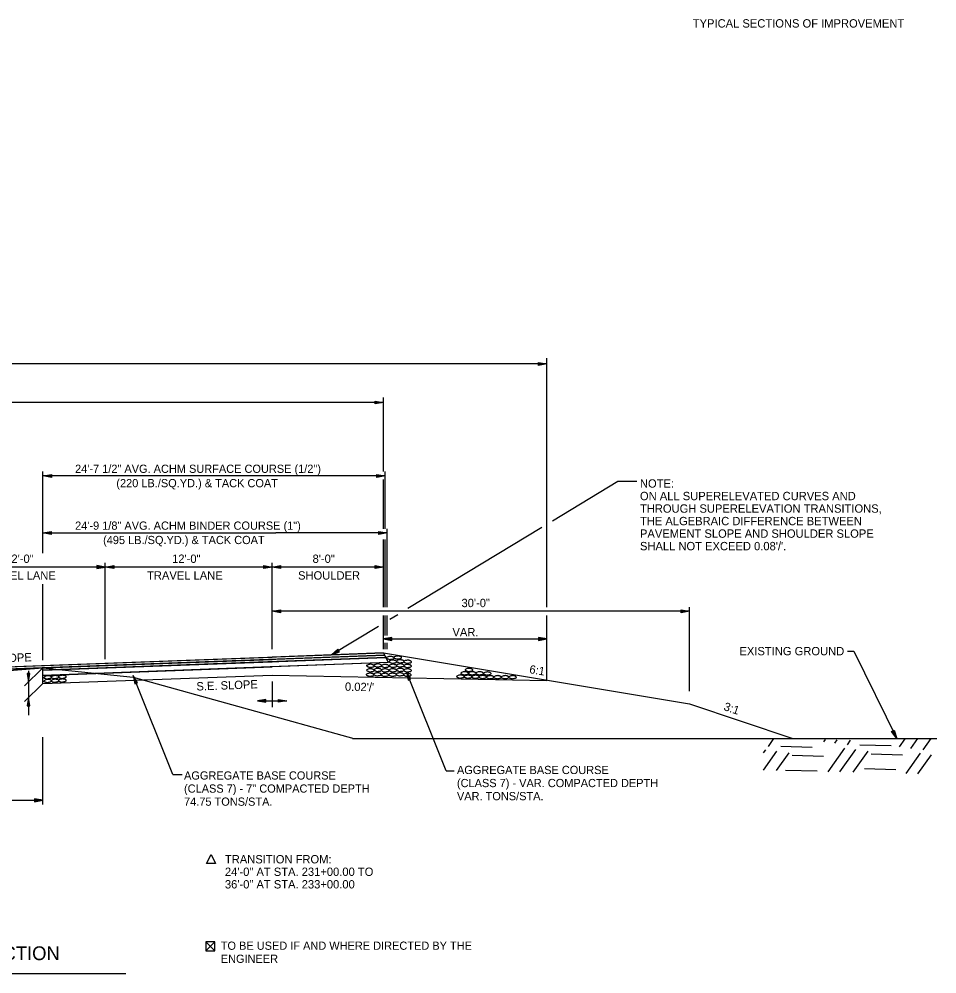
# Model space of a CAD drawing. Extents: x 1461846 to 1462006, y 1686171 to 1686805.
# Drawn here: x 1461938.5 to 1462004.5, y 1686332.5 to 1686401.2 of the extents above; entities that cross this region are included whole.
import ezdxf

# ---------------------------------------------------------------- set-up
doc = ezdxf.new("R2010")
doc.units = 0
for name, color, linetype in [('1', 7, 'Continuous'), ('10', 7, 'Continuous'), ('12', 7, 'Continuous'), ('19', 7, 'Continuous'), ('20', 7, 'Continuous'), ('3', 7, 'Continuous'), ('42', 7, 'Continuous'), ('R_Draft', 7, 'Continuous')]:
    doc.layers.add(name, color=color, linetype=linetype)

# ---------------------------------------------------------------- blocks, each defined once
blk = doc.blocks.new('ROCKS')
at = {"layer": '1'}
blk.add_spline([(0.013, 0.06), (0.053, 0.053), (0.107, 0.033), (0.133, 0.013), (0.133, -0.007), (0.12, -0.033), (0.107, -0.04), (0.073, -0.053), (0.033, -0.067), (0.013, -0.067), (-0.02, -0.06), (-0.06, -0.053), (-0.087, -0.047), (-0.113, -0.02), (-0.113, -0.007), (-0.107, 0.02), (-0.087, 0.033), (-0.067, 0.047), (-0.033, 0.053), (-0.02, 0.06), (0.013, 0.06)], degree=3, dxfattribs=at)

msp = doc.modelspace()

# ---------------------------------------------------------------- linework, layer by layer
at = {"layer": '10'}
for p, q in [((1461951.906, 1686334.857), (1461952.547, 1686334.216)), ((1461952.547, 1686334.857), (1461951.906, 1686334.216)), ((1461952.287, 1686334.216), (1461952.298, 1686334.216))]:
    msp.add_line(p, q, dxfattribs=at)
for points in [[(1461952.601, 1686340.482), (1461951.959, 1686340.482), (1461952.28, 1686341.123), (1461952.601, 1686340.482)], [(1461952.298, 1686334.216), (1461952.547, 1686334.216), (1461952.547, 1686334.857), (1461951.906, 1686334.857), (1461951.906, 1686334.216), (1461952.287, 1686334.216)]]:
    msp.add_lwpolyline(points, dxfattribs=at)
at = {"layer": '19'}
for p, q in [((1461964.68, 1686355.622), (1461965.028, 1686354.927)), ((1461964.844, 1686355.295), (1461965.028, 1686354.927)), ((1461940.18, 1686354.007), (1461940.18, 1686354.382)), ((1461940.18, 1686354.382), (1461940.18, 1686354.382)), ((1461939.261, 1686354.147), (1461939.051, 1686354.147)), ((1461939.051, 1686354.147), (1461939.156, 1686353.547)), ((1461939.106, 1686354.147), (1461939.141, 1686353.707)), ((1461939.156, 1686353.547), (1461939.261, 1686354.147)), ((1461939.171, 1686353.707), (1461939.211, 1686354.147)), ((1461940.18, 1686354.007), (1461940.18, 1686354.007)), ((1461949.537, 1686346.872), (1461946.684, 1686353.991)), ((1461947.004, 1686353.475), (1461946.684, 1686353.991)), ((1461946.684, 1686353.991), (1461946.811, 1686353.395)), ((1461946.732, 1686353.839), (1461946.859, 1686353.418)), ((1461946.958, 1686353.457), (1461946.759, 1686353.85)), ((1461969.184, 1686347.148), (1461966.332, 1686354.268)), ((1461966.651, 1686353.751), (1461966.332, 1686354.268)), ((1461966.332, 1686354.268), (1461966.458, 1686353.672)), ((1461966.379, 1686354.116), (1461966.506, 1686353.695)), ((1461966.605, 1686353.733), (1461966.406, 1686354.126)), ((1461966.458, 1686353.672), (1461966.651, 1686353.751)), ((1461946.811, 1686353.395), (1461947.004, 1686353.475)), ((1461939.156, 1686352.422), (1461939.051, 1686351.822)), ((1461939.141, 1686352.262), (1461939.101, 1686351.822)), ((1461939.261, 1686351.822), (1461939.156, 1686352.422)), ((1461939.206, 1686351.822), (1461939.171, 1686352.262)), ((1461939.051, 1686351.822), (1461939.261, 1686351.822)), ((1461992.352, 1686348.904), (1461992.758, 1686349.478)), ((1461993.241, 1686348.922), (1461995.5, 1686348.845)), ((1461996.347, 1686349.241), (1461996.456, 1686349.389)), ((1461997.139, 1686349.13), (1461997.311, 1686349.37)), ((1461998.032, 1686349.016), (1461998.266, 1686349.349)), ((1461998.92, 1686349.024), (1462001.18, 1686348.958)), ((1462001.793, 1686348.869), (1462002.2, 1686349.451)), ((1462002.586, 1686348.758), (1462003.091, 1686349.464)), ((1462003.479, 1686348.644), (1462004.061, 1686349.478)), ((1461991.993, 1686347.196), (1461992.953, 1686348.555)), ((1461992.001, 1686348.445), (1461992.16, 1686348.667)), ((1461992.948, 1686347.175), (1461993.845, 1686348.442)), ((1461994.066, 1686348.272), (1461996.324, 1686348.196)), ((1461996.646, 1686347.086), (1461997.84, 1686348.779)), ((1461997.501, 1686347.068), (1461998.633, 1686348.668)), ((1461998.456, 1686347.047), (1461999.525, 1686348.554)), ((1461999.734, 1686348.376), (1462002.004, 1686348.308)), ((1462002.255, 1686346.955), (1462003.287, 1686348.406)), ((1462003.11, 1686346.937), (1462004.079, 1686348.295)), ((1461949.537, 1686346.872), (1461950.214, 1686346.872)), ((1461969.184, 1686347.148), (1461969.756, 1686347.148)), ((1461993.587, 1686347.204), (1461995.856, 1686347.137)), ((1461999.267, 1686347.316), (1462001.525, 1686347.24))]:
    msp.add_line(p, q, dxfattribs=at)
for points in [[(1461964.762, 1686355.458), (1461960.956, 1686355.318), (1461940.777, 1686354.571), (1461921.639, 1686353.863), (1461914.019, 1686353.581), (1461903.26, 1686353.183), (1461897.595, 1686352.973), (1461895.595, 1686352.893), (1461889.595, 1686352.653), (1461889.595, 1686352.653), (1461889.595, 1686352.653), (1461889.68, 1686352.823), (1461889.68, 1686352.823), (1461889.68, 1686352.823), (1461895.545, 1686353.058), (1461903.665, 1686353.365), (1461913.994, 1686353.747), (1461921.643, 1686354.03), (1461940.732, 1686354.736), (1461960.903, 1686355.482), (1461964.68, 1686355.622)], [(1461964.844, 1686355.295), (1461955.038, 1686354.932), (1461940.18, 1686354.382), (1461940.18, 1686354.382), (1461940.18, 1686354.382), (1461940.18, 1686354.549), (1461940.18, 1686354.549), (1461940.18, 1686354.549), (1461954.984, 1686355.097), (1461964.762, 1686355.458)]]:
    msp.add_lwpolyline(points, close=True, dxfattribs=at)
for points in [[(1461940.18, 1686354.382), (1461940.18, 1686354.382), (1461940.18, 1686354.382), (1461956.513, 1686354.987), (1461964.844, 1686355.295)], [(1461965.028, 1686354.927), (1461956.534, 1686354.612), (1461940.18, 1686354.007), (1461940.18, 1686354.007), (1461940.18, 1686354.007)]]:
    msp.add_lwpolyline(points, dxfattribs=at)
at = {"layer": '20'}
for p, q in [((1461976.425, 1686376.393), (1461879.904, 1686376.393)), ((1461975.825, 1686376.288), (1461975.825, 1686376.498)), ((1461975.825, 1686376.498), (1461976.425, 1686376.393)), ((1461975.825, 1686376.443), (1461976.265, 1686376.408)), ((1461976.425, 1686376.393), (1461975.825, 1686376.288)), ((1461976.265, 1686376.378), (1461975.825, 1686376.338)), ((1461976.425, 1686367.782), (1461976.425, 1686376.797)), ((1461964.68, 1686373.624), (1461889.68, 1686373.624)), ((1461964.08, 1686373.519), (1461964.08, 1686373.729)), ((1461964.08, 1686373.729), (1461964.68, 1686373.624)), ((1461964.08, 1686373.674), (1461964.52, 1686373.639)), ((1461964.68, 1686373.624), (1461964.08, 1686373.519)), ((1461964.52, 1686373.609), (1461964.08, 1686373.569)), ((1461964.68, 1686368.657), (1461964.68, 1686373.976)), ((1461940.18, 1686362.79), (1461940.18, 1686368.657)), ((1461956.805, 1686368.339), (1461940.18, 1686368.339)), ((1461940.208, 1686368.339), (1461940.808, 1686368.444)), ((1461940.808, 1686368.234), (1461940.208, 1686368.339)), ((1461940.368, 1686368.354), (1461940.808, 1686368.389)), ((1461940.808, 1686368.284), (1461940.368, 1686368.324)), ((1461940.808, 1686368.444), (1461940.808, 1686368.234)), ((1461964.805, 1686368.339), (1461956.805, 1686368.339)), ((1461964.205, 1686368.234), (1461964.205, 1686368.444)), ((1461964.205, 1686368.444), (1461964.805, 1686368.339)), ((1461964.205, 1686368.389), (1461964.645, 1686368.354)), ((1461964.805, 1686368.339), (1461964.205, 1686368.234)), ((1461964.645, 1686368.324), (1461964.205, 1686368.284)), ((1461964.68, 1686364.538), (1461964.68, 1686368.079)), ((1461964.805, 1686364.538), (1461964.805, 1686368.657)), ((1461976.425, 1686358.913), (1461976.425, 1686367.782)), ((1461940.18, 1686364.246), (1461940.78, 1686364.351)), ((1461940.78, 1686364.141), (1461940.18, 1686364.246)), ((1461940.18, 1686364.246), (1461956.94, 1686364.246)), ((1461940.34, 1686364.261), (1461940.78, 1686364.296)), ((1461940.78, 1686364.191), (1461940.34, 1686364.231)), ((1461940.78, 1686364.351), (1461940.78, 1686364.141)), ((1461964.94, 1686364.246), (1461956.94, 1686364.246)), ((1461964.34, 1686364.141), (1461964.34, 1686364.351)), ((1461964.34, 1686364.351), (1461964.94, 1686364.246)), ((1461964.34, 1686364.296), (1461964.78, 1686364.261)), ((1461964.94, 1686364.246), (1461964.34, 1686364.141)), ((1461964.78, 1686364.231), (1461964.34, 1686364.191)), ((1461964.94, 1686361.499), (1461964.94, 1686364.538)), ((1461964.68, 1686362.092), (1461964.68, 1686363.78)), ((1461964.805, 1686358.913), (1461964.805, 1686363.78)), ((1461964.94, 1686358.913), (1461964.94, 1686361.499)), ((1461964.805, 1686356.872), (1461964.805, 1686358.313)), ((1461964.94, 1686356.872), (1461964.94, 1686358.313)), ((1461976.425, 1686353.64), (1461976.425, 1686358.313)), ((1461965.28, 1686356.735), (1461964.68, 1686356.63)), ((1461964.68, 1686356.63), (1461976.431, 1686356.63)), ((1461964.68, 1686356.63), (1461965.28, 1686356.525)), ((1461964.805, 1686355.894), (1461964.805, 1686356.345)), ((1461965.28, 1686356.68), (1461964.84, 1686356.645)), ((1461964.84, 1686356.615), (1461965.28, 1686356.575)), ((1461964.94, 1686355.894), (1461964.94, 1686356.345)), ((1461965.28, 1686356.525), (1461965.28, 1686356.735)), ((1461975.831, 1686356.735), (1461975.831, 1686356.525)), ((1461976.431, 1686356.63), (1461975.831, 1686356.735)), ((1461976.271, 1686356.645), (1461975.831, 1686356.68)), ((1461975.831, 1686356.525), (1461976.431, 1686356.63)), ((1461975.831, 1686356.575), (1461976.271, 1686356.615)), ((1461940.18, 1686354.549), (1461938.857, 1686353.254)), ((1461940.18, 1686353.424), (1461938.857, 1686352.129))]:
    msp.add_line(p, q, dxfattribs=at)
msp.add_lwpolyline([(1461939.156, 1686354.339), (1461939.156, 1686351.141)], dxfattribs=at)
at = {"layer": '3'}
msp.add_line((1461946.153, 1686332.55), (1461908.207, 1686332.55), dxfattribs=at)
at = {"layer": 'R_Draft'}
for p, q in [((1461944.08, 1686361.897), (1461944.08, 1686361.687)), ((1461944.68, 1686361.792), (1461944.08, 1686361.897)), ((1461944.52, 1686361.807), (1461944.08, 1686361.842)), ((1461944.68, 1686355.176), (1461944.68, 1686362.092)), ((1461944.68, 1686361.792), (1461945.28, 1686361.897)), ((1461944.84, 1686361.807), (1461945.28, 1686361.842)), ((1461945.28, 1686361.897), (1461945.28, 1686361.687)), ((1461956.08, 1686361.687), (1461956.08, 1686361.897)), ((1461956.08, 1686361.897), (1461956.68, 1686361.792)), ((1461956.08, 1686361.842), (1461956.52, 1686361.807)), ((1461956.68, 1686355.894), (1461956.68, 1686362.092)), ((1461956.68, 1686361.792), (1461957.28, 1686361.897)), ((1461956.84, 1686361.807), (1461957.28, 1686361.842)), ((1461957.28, 1686361.897), (1461957.28, 1686361.687)), ((1461964.08, 1686361.687), (1461964.08, 1686361.897)), ((1461964.08, 1686361.897), (1461964.68, 1686361.792)), ((1461964.08, 1686361.842), (1461964.52, 1686361.807)), ((1461964.68, 1686358.913), (1461964.68, 1686362.092)), ((1461944.68, 1686361.792), (1461932.68, 1686361.792)), ((1461944.08, 1686361.687), (1461944.68, 1686361.792)), ((1461944.08, 1686361.737), (1461944.52, 1686361.777)), ((1461956.68, 1686361.792), (1461944.68, 1686361.792)), ((1461945.28, 1686361.687), (1461944.68, 1686361.792)), ((1461945.28, 1686361.737), (1461944.84, 1686361.777)), ((1461956.68, 1686361.792), (1461956.08, 1686361.687)), ((1461956.52, 1686361.777), (1461956.08, 1686361.737)), ((1461964.68, 1686361.792), (1461956.68, 1686361.792)), ((1461957.28, 1686361.687), (1461956.68, 1686361.792)), ((1461957.28, 1686361.737), (1461956.84, 1686361.777)), ((1461964.68, 1686361.792), (1461964.08, 1686361.687)), ((1461964.52, 1686361.777), (1461964.08, 1686361.737)), ((1461940.18, 1686355.098), (1461940.18, 1686360.554)), ((1461956.68, 1686358.613), (1461957.28, 1686358.718)), ((1461986.68, 1686358.613), (1461956.68, 1686358.613)), ((1461957.28, 1686358.508), (1461956.68, 1686358.613)), ((1461956.84, 1686358.628), (1461957.28, 1686358.663)), ((1461957.28, 1686358.558), (1461956.84, 1686358.598)), ((1461957.28, 1686358.718), (1461957.28, 1686358.508)), ((1461986.08, 1686358.508), (1461986.08, 1686358.718)), ((1461986.08, 1686358.718), (1461986.68, 1686358.613)), ((1461986.08, 1686358.663), (1461986.52, 1686358.628)), ((1461986.68, 1686358.613), (1461986.08, 1686358.508)), ((1461986.52, 1686358.598), (1461986.08, 1686358.558)), ((1461986.68, 1686352.87), (1461986.68, 1686358.913)), ((1461964.68, 1686355.894), (1461964.68, 1686358.313)), ((1461961.404, 1686355.889), (1461960.949, 1686355.484)), ((1461960.949, 1686355.484), (1461961.515, 1686355.71)), ((1461961.433, 1686355.842), (1461961.077, 1686355.581)), ((1461961.093, 1686355.555), (1461961.488, 1686355.753)), ((1461961.515, 1686355.71), (1461961.404, 1686355.889)), ((1461964.68, 1686355.622), (1461956.68, 1686355.326)), ((1461964.762, 1686355.458), (1461956.68, 1686355.159)), ((1461964.844, 1686355.295), (1461956.68, 1686354.993)), ((1461964.68, 1686355.622), (1461986.68, 1686351.955)), ((1461940.18, 1686353.424), (1461940.18, 1686354.549)), ((1461965.028, 1686354.927), (1461956.68, 1686354.618)), ((1461956.68, 1686354.034), (1461976.425, 1686353.64)), ((1461956.68, 1686353.562), (1461956.68, 1686351.726)), ((1461956.232, 1686352.283), (1461955.632, 1686352.178)), ((1461956.232, 1686352.228), (1461955.792, 1686352.193)), ((1461956.232, 1686352.073), (1461956.232, 1686352.283)), ((1461957.127, 1686352.073), (1461957.127, 1686352.283)), ((1461957.127, 1686352.283), (1461957.727, 1686352.178)), ((1461957.127, 1686352.228), (1461957.567, 1686352.193)), ((1461955.632, 1686352.178), (1461956.232, 1686352.073)), ((1461955.632, 1686352.178), (1461957.727, 1686352.178)), ((1461955.792, 1686352.163), (1461956.232, 1686352.123)), ((1461957.727, 1686352.178), (1461957.127, 1686352.073)), ((1461957.567, 1686352.163), (1461957.127, 1686352.123)), ((1461986.68, 1686351.955), (1461994.114, 1686349.478)), ((1461940.18, 1686344.733), (1461940.18, 1686349.577)), ((1462001.215, 1686349.966), (1462001.402, 1686350.06)), ((1462001.579, 1686349.478), (1462001.215, 1686349.966)), ((1462001.498, 1686349.614), (1462001.265, 1686349.986)), ((1462001.363, 1686350.036), (1462001.52, 1686349.628)), ((1462001.402, 1686350.06), (1462001.579, 1686349.478)), ((1461962.444, 1686349.478), (1462004.472, 1686349.478)), ((1461912.763, 1686345.033), (1461940.18, 1686345.033)), ((1461939.58, 1686345.138), (1461939.58, 1686344.928)), ((1461940.18, 1686345.033), (1461939.58, 1686345.138)), ((1461940.02, 1686345.048), (1461939.58, 1686345.083)), ((1461939.58, 1686344.928), (1461940.18, 1686345.033)), ((1461939.58, 1686344.978), (1461940.02, 1686345.018))]:
    msp.add_line(p, q, dxfattribs=at)
for points in [[(1461982.892, 1686367.933), (1461981.53, 1686367.933), (1461976.842, 1686365.098)], [(1461976.067, 1686364.629), (1461966.44, 1686358.806)], [(1461965.711, 1686358.364), (1461965.142, 1686358.021)], [(1461964.318, 1686357.522), (1461960.949, 1686355.484)], [(1461998.043, 1686355.75), (1461998.497, 1686355.75), (1462001.579, 1686349.478)], [(1461897.68, 1686353.143), (1461927.18, 1686354.235), (1461956.68, 1686355.326)], [(1461897.68, 1686352.976), (1461927.18, 1686354.068), (1461956.68, 1686355.159)], [(1461940.18, 1686354.382), (1461956.68, 1686354.993)], [(1461942.68, 1686354.641), (1461956.68, 1686355.159)], [(1461847.362, 1686353.269), (1461867.322, 1686352.565), (1461882.06, 1686349.033), (1461884.194, 1686348.879), (1461888.604, 1686349.011), (1461896.486, 1686349.242), (1461912.763, 1686353.534), (1461918.661, 1686353.486), (1461934.122, 1686354.079), (1461940.18, 1686354.549), (1461946.68, 1686353.887), (1461962.552, 1686349.481)], [(1461940.179, 1686354.007), (1461956.68, 1686354.618)], [(1461940.18, 1686353.424), (1461956.68, 1686354.034)], [(1461951.959, 1686340.482), (1461952.28, 1686341.123), (1461952.601, 1686340.482), (1461951.959, 1686340.482)]]:
    msp.add_lwpolyline(points, dxfattribs=at)

# ---------------------------------------------------------------- block references
at = {"layer": '19'}
for p, xscale, yscale, rotation in [((1461965.192, 1686355.272), 2.061136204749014, -2.0611362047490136, 178.31754410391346), ((1461965.377, 1686355.001), 2.061136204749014, -2.0611362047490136, 178.31754410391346), ((1461965.723, 1686355.299), 2.061136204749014, -2.0611362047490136, 178.31754410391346), ((1461965.907, 1686355.028), 2.061136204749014, -2.0611362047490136, 178.31754410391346), ((1461966.435, 1686354.993), 2.061136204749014, -2.0611362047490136, 178.31754410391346), ((1461963.763, 1686354.701), 2.061136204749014, -2.0611362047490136, 178.31754410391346), ((1461963.763, 1686354.381), 2.061136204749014, -2.0611362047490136, 178.31754410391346), ((1461964.293, 1686354.728), 2.061136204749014, -2.0611362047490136, 178.31754410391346), ((1461964.293, 1686354.407), 2.061136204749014, -2.0611362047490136, 178.31754410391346), ((1461964.821, 1686354.693), 2.061136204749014, -2.0611362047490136, 178.31754410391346), ((1461964.821, 1686354.373), 2.061136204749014, -2.0611362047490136, 178.31754410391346), ((1461965.377, 1686354.701), 2.061136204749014, -2.0611362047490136, 178.31754410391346), ((1461965.377, 1686354.381), 2.061136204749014, -2.0611362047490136, 178.31754410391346), ((1461965.907, 1686354.728), 2.061136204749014, -2.0611362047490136, 178.31754410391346), ((1461965.907, 1686354.407), 2.061136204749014, -2.0611362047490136, 178.31754410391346), ((1461966.435, 1686354.693), 2.061136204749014, -2.0611362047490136, 178.31754410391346), ((1461966.435, 1686354.373), 2.061136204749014, -2.0611362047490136, 178.31754410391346), ((1461970.542, 1686354.166), 2.061136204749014, -2.061136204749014, 180), ((1461970.847, 1686354.405), 2.061136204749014, -2.061136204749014, 180), ((1461971.084, 1686354.166), 2.061136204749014, -2.061136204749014, 180), ((1461971.618, 1686354.166), 2.061136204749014, -2.061136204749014, 180), ((1461940.553, 1686353.879), 2.0611362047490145, -2.0611362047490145, -176.23624371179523), ((1461940.553, 1686353.617), 2.0611362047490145, -2.0611362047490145, -176.23624371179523), ((1461941.082, 1686353.894), 2.0611362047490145, -2.0611362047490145, -176.23624371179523), ((1461941.083, 1686353.632), 2.0611362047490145, -2.0611362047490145, -176.23624371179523), ((1461941.611, 1686353.91), 2.0611362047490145, -2.0611362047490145, -176.23624371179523), ((1461941.611, 1686353.648), 2.0611362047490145, -2.0611362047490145, -176.23624371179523), ((1461963.738, 1686354.062), 2.061136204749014, -2.0611362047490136, 178.31754410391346), ((1461964.269, 1686354.089), 2.061136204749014, -2.0611362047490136, 178.31754410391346), ((1461964.797, 1686354.054), 2.061136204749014, -2.0611362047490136, 178.31754410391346), ((1461965.352, 1686354.062), 2.061136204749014, -2.0611362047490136, 178.31754410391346), ((1461965.883, 1686354.089), 2.061136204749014, -2.0611362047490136, 178.31754410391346), ((1461966.411, 1686354.054), 2.061136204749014, -2.0611362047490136, 178.31754410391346), ((1461970.234, 1686353.933), 2.061136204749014, -2.061136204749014, 180), ((1461970.779, 1686353.924), 2.061136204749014, -2.061136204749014, 180), ((1461971.313, 1686353.914), 2.061136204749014, -2.061136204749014, 180), ((1461971.837, 1686353.901), 2.061136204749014, -2.061136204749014, 180), ((1461972.16, 1686354.15), 2.061136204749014, -2.061136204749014, 180), ((1461972.368, 1686353.886), 2.061136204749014, -2.061136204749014, 180), ((1461972.895, 1686353.886), 2.061136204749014, -2.061136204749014, 180), ((1461973.439, 1686353.886), 2.061136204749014, -2.061136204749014, 180), ((1461973.977, 1686353.886), 2.061136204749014, -2.061136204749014, 180)]:
    msp.add_blockref('ROCKS', p, dxfattribs=dict(at, xscale=xscale, yscale=yscale, rotation=rotation))

# ---------------------------------------------------------------- texts
at = {"layer": '1'}
msp.add_text('TYPICAL SECTIONS OF IMPROVEMENT', height=0.6, dxfattribs=at).set_placement((1461986.919, 1686400.572))
at = {"layer": '10'}
for s, height, p in [('TO BE USED IF AND WHERE DIRECTED BY THE ', 0.59001, (1461952.979, 1686334.283)), ('ENGINEER', 0.59, (1461952.979, 1686333.343))]:
    msp.add_text(s, height=height, rotation=360, dxfattribs=at).set_placement(p)
at = {"layer": '12'}
msp.add_text('SUPERELEVATED NOTCH AND WIDEN SECTION', height=0.98999, rotation=0.00462, dxfattribs=at).set_placement((1461910.658, 1686333.537))
at = {"layer": '19'}
for s, p in [('AGGREGATE BASE COURSE', (1461969.962, 1686346.914)), ('AGGREGATE BASE COURSE', (1461950.339, 1686346.517)), ('(CLASS 7) - 7" COMPACTED DEPTH', (1461950.339, 1686345.577)), ('(CLASS 7) - VAR. COMPACTED DEPTH', (1461969.962, 1686345.974)), ('VAR. TONS/STA.', (1461969.962, 1686345.034)), ('74.75 TONS/STA.', (1461950.339, 1686344.637))]:
    msp.add_text(s, height=0.59001, dxfattribs=at).set_placement(p)
at = {"layer": '42'}
for s, p in [('24\'-7 1/2" AVG. ACHM SURFACE COURSE (1/2")', (1461942.506, 1686368.564)), ('(220 LB./SQ.YD.) & TACK COAT', (1461945.472, 1686367.531)), ('24\'-9 1/8" AVG. ACHM BINDER COURSE (1")', (1461942.506, 1686364.476)), ('(495 LB./SQ.YD.) & TACK COAT', (1461944.519, 1686363.444))]:
    msp.add_text(s, height=0.59001, dxfattribs=at).set_placement(p)
at = {"layer": 'R_Draft'}
for s, p in [('NOTE:', (1461983.12, 1686367.5)), ('ON ALL SUPERELEVATED CURVES AND', (1461983.12, 1686366.6)), ('THROUGH SUPERELEVATION TRANSITIONS,', (1461983.12, 1686365.7)), ('THE ALGEBRAIC DIFFERENCE BETWEEN', (1461983.12, 1686364.8)), ('PAVEMENT SLOPE AND SHOULDER SLOPE', (1461983.12, 1686363.9)), ("SHALL NOT EXCEED 0.08'/'.", (1461983.12, 1686363)), ('12\'-0"', (1461937.482, 1686362.092)), ('12\'-0"', (1461949.482, 1686362.092)), ('8\'-0"', (1461959.581, 1686362.092)), ('TRAVEL LANE', (1461935.68, 1686360.892)), ('TRAVEL LANE', (1461947.68, 1686360.892)), ('SHOULDER', (1461958.537, 1686360.892)), ('30\'-0"', (1461970.289, 1686358.913)), ('EXISTING GROUND', (1461990.275, 1686355.45))]:
    msp.add_text(s, height=0.6, dxfattribs=at).set_placement(p)
for s, rotation, p in [('VAR.', 360, (1461969.639, 1686356.813)), ('S.E. SLOPE', 2.11898, (1461934.987, 1686354.856)), ('6:1', 350.51747, (1461975.134, 1686354.172)), ('S.E. SLOPE', 2.11898, (1461951.239, 1686352.915)), ("0.02'/'", 358.85424, (1461961.906, 1686352.904)), ('3:1', 341.56505, (1461989.094, 1686351.523)), ('TRANSITION FROM:', 0.00462, (1461953.279, 1686340.491)), ('24\'-0" AT STA. 231+00.00 TO ', 0.00462, (1461953.279, 1686339.591)), ('36\'-0" AT STA. 233+00.00', 0.00462, (1461953.279, 1686338.691))]:
    msp.add_text(s, height=0.6, rotation=rotation, dxfattribs=at).set_placement(p)

doc.saveas('drawing.dxf')
